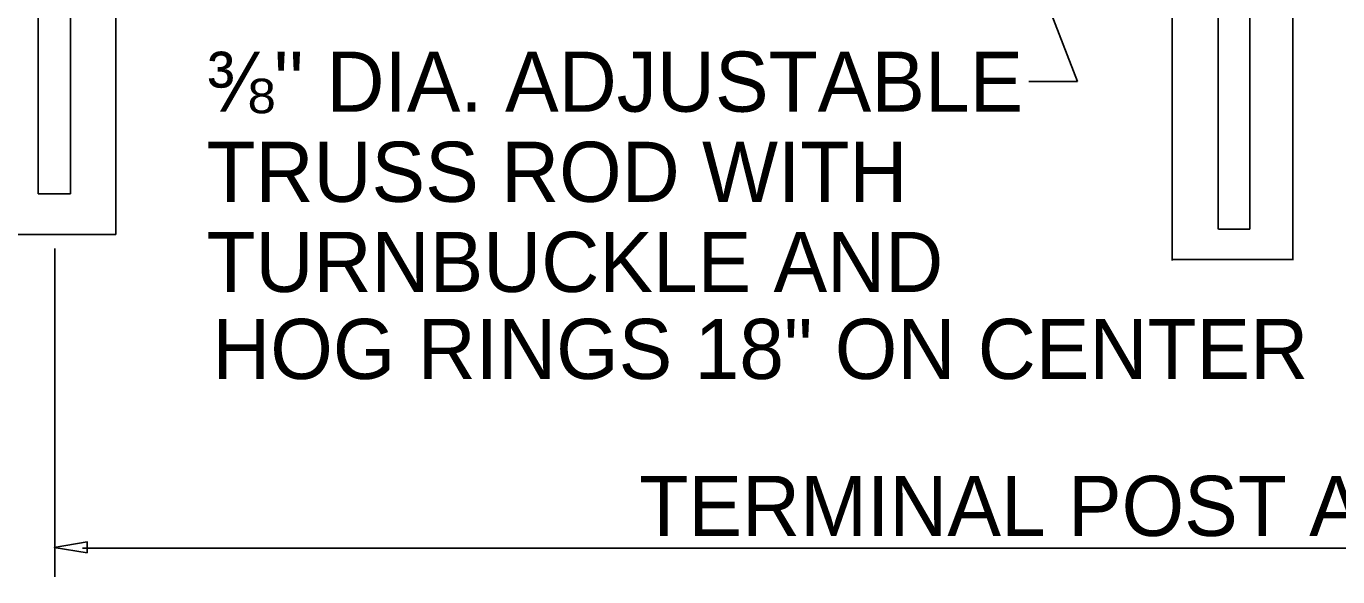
# Model space of a CAD drawing. Extents: x 0 to 2.85, y -0.1 to 1.83.
# Drawn here: x 0.3535 to 0.5717, y 1.1735 to 1.2652 of the extents above; entities that cross this region are included whole.
import ezdxf

# ---------------------------------------------------------------- set-up
doc = ezdxf.new("R2010")
doc.units = 0
for name, color, linetype in [('CT_CSHT_GeneralLabel', 7, 'Continuous'), ('CT_Dimensions', 7, 'Continuous'), ('sb_Chainlink Fence', 7, 'Continuous'), ('sb_Existing Concrete', 7, 'Continuous'), ('sb_Existing Structural Steel', 7, 'Continuous')]:
    doc.layers.add(name, color=color, linetype=linetype)

msp = doc.modelspace()

# ---------------------------------------------------------------- linework, layer by layer
at = {"layer": 'CT_Dimensions'}
for p, q in [((0.35829, 1.22815), (0.35829, 1.17354)), ((0.36289, 1.17828), (0.74643, 1.17828))]:
    msp.add_line(p, q, dxfattribs=at)
msp.add_lwpolyline([(0.36369, 1.17751), (0.3582, 1.17842), (0.36369, 1.17934)], close=True, dxfattribs=at)
at = {"layer": 'sb_Chainlink Fence'}
for p, q in [((0.52845, 1.25598), (0.49157, 1.35127)), ((0.52031, 1.25598), (0.52845, 1.25598))]:
    msp.add_line(p, q, dxfattribs=at)
at = {"layer": 'sb_Existing Concrete'}
for p, q in [((0.36844, 1.2305), (0.36843, 1.28206)), ((0.54418, 1.22616), (0.54418, 1.28198)), ((0.56424, 1.22624), (0.56424, 1.28205)), ((0.34823, 1.2305), (0.36844, 1.2305)), ((0.54428, 1.22632), (0.56418, 1.22632))]:
    msp.add_line(p, q, dxfattribs=at)
at = {"layer": 'sb_Existing Structural Steel'}
for p, q in [((0.35552, 1.23729), (0.35552, 1.28461)), ((0.36087, 1.23729), (0.36087, 1.28461)), ((0.55182, 1.2314), (0.55182, 1.28422)), ((0.55707, 1.23137), (0.55707, 1.28419)), ((0.35552, 1.23729), (0.36087, 1.23729)), ((0.55187, 1.23139), (0.55707, 1.23139))]:
    msp.add_line(p, q, dxfattribs=at)

# ---------------------------------------------------------------- texts
at = {"layer": 'CT_CSHT_GeneralLabel'}
msp.add_text('TERMINAL POST ASSEMBLY', height=0.01, dxfattribs=at).set_placement((0.45552, 1.18034))
at = {"layer": 'CT_Dimensions'}
for s, p in [("⅜'' DIA. ADJUSTABLE ", (0.3835, 1.25094)), ('TRUSS ROD WITH', (0.3835, 1.23594)), ('TURNBUCKLE AND', (0.3835, 1.22094)), ('HOG RINGS 18" ON CENTER', (0.38448, 1.20646))]:
    msp.add_text(s, height=0.01, dxfattribs=at).set_placement(p)

doc.saveas('drawing.dxf')
